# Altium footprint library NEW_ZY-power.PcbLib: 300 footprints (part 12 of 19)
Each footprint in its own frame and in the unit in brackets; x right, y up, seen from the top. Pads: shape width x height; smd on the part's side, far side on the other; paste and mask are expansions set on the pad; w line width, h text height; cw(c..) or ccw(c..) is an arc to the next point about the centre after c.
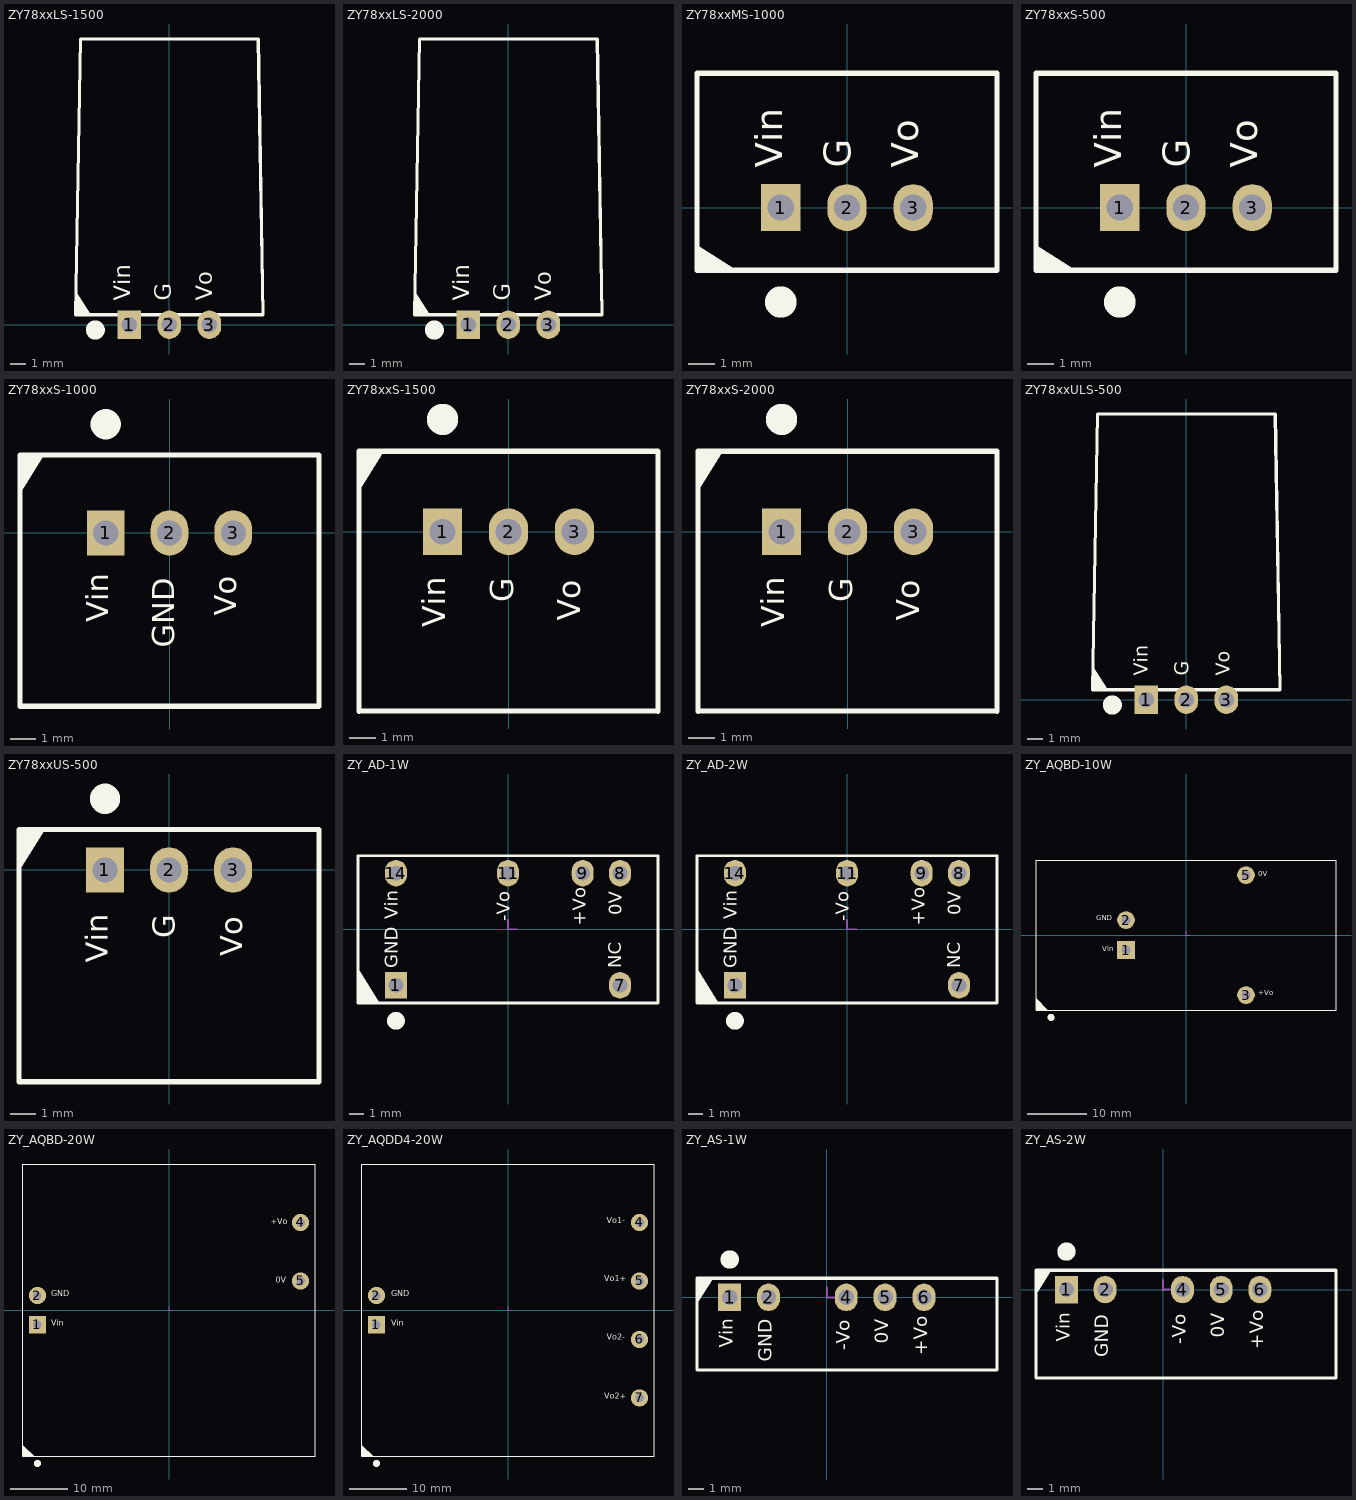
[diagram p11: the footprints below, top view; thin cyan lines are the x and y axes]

## ZY78xxLS-1500 [mm]
height 10
pads (3):
  rect 1.5x1.8 hole 1: 1(-2.54,0)
  oval 1.5x1.8 hole 1: 2(0,0) 3(2.54,0)
Top Overlay:
  circle w1: c-4.699,-0.327 r0.1
  region: -5.991,2.229 -5.991,0.644 -4.997,0.644
  lines w0.2: -5.95,0.644 -5.645,18.144 5.645,18.144 5.95,0.644 -5.95,0.644
  text "Vin" at -2.134,1.524 h1.78
  text "G" at 0.483,1.524 h1.78
  text "Vo" at 3.073,1.524 h1.78

## ZY78xxLS-2000 [mm]
height 10
pads (3):
  rect 1.5x1.8 hole 1: 1(-2.54,0)
  oval 1.5x1.8 hole 1: 2(0,0) 3(2.54,0)
Top Overlay:
  circle w1: c-4.699,-0.327 r0.1
  region: -5.991,2.229 -5.991,0.644 -4.997,0.644
  lines w0.2: -5.95,0.644 -5.645,18.144 5.645,18.144 5.95,0.644 -5.95,0.644
  text "Vin" at -2.134,1.524 h1.78
  text "G" at 0.483,1.524 h1.78
  text "Vo" at 3.073,1.524 h1.78

## ZY78xxMS-1000 [mm]
height 10.2
pads (3):
  rect 1.5x1.8 hole 1: 1(-2.54,0)
  oval 1.5x1.8 hole 1: 2(0,0) 3(2.54,0)
Top Overlay:
  circle w1: c-2.54,-3.625 r0.1
  region: -4.168,-2.441 -5.753,-2.441 -5.753,-1.447
  lines w0.2: -5.753,-2.4 5.753,-2.4 5.753,5.15 -5.753,5.15 -5.753,-2.4
  text "Vin" at -2.134,1.524 h1.78
  text "G" at 0.483,1.524 h1.78
  text "Vo" at 3.073,1.524 h1.78

## ZY78xxS-500 [mm]
pads (3):
  rect 1.5x1.8 hole 1: 1(-2.54,0)
  oval 1.5x1.8 hole 1: 2(0,0) 3(2.54,0)
Top Overlay:
  circle w1: c-2.54,-3.625 r0.1
  region: -4.168,-2.441 -5.753,-2.441 -5.753,-1.447
  lines w0.2: -5.753,-2.4 5.753,-2.4 5.753,5.15 -5.753,5.15 -5.753,-2.4
  text "Vo" at 3.073,1.524 h1.78
  text "G" at 0.483,1.524 h1.78
  text "Vin" at -2.134,1.524 h1.78

## ZY78xxS-1000 [mm]
height 17.5
pads (3):
  rect 1.5x1.8 hole 1: 1(-2.54,0)
  oval 1.5x1.8 hole 1: 2(0,0) 3(2.54,0)
Top Overlay:
  circle w1: c-2.54,4.325 r0.1
  region: -5.991,1.514 -5.991,3.1 -4.997,3.1
  lines w0.2: -5.95,-6.9 5.95,-6.9 5.95,3.1 -5.95,3.1 -5.95,-6.9
  text "Vo" at 2.946,-3.302 h1.52
  text "GND" at 0.483,-4.572 h1.52
  text "Vin" at -2.134,-3.562 h1.52

## ZY78xxS-1500 [mm]
height 17.5
pads (3):
  rect 1.5x1.8 hole 1: 1(-2.54,0)
  oval 1.5x1.8 hole 1: 2(0,0) 3(2.54,0)
Top Overlay:
  circle w1: c-2.54,4.325 r0.1
  region: -5.794,1.514 -5.794,3.1 -4.801,3.1
  lines w0.2: -5.753,-6.908 -5.753,3.1 5.753,3.1 5.753,-6.908 ; -5.753,-6.9 5.753,-6.9
  text "Vo" at 3.073,-3.423 h1.52
  text "G" at 0.483,-2.714 h1.52
  text "Vin" at -2.134,-3.683 h1.52

## ZY78xxS-2000 [mm]
height 17.5
pads (3):
  rect 1.5x1.8 hole 1: 1(-2.54,0)
  oval 1.5x1.8 hole 1: 2(0,0) 3(2.54,0)
Top Overlay:
  circle w1: c-2.54,4.325 r0.1
  region: -5.794,1.514 -5.794,3.1 -4.801,3.1
  lines w0.2: -5.753,-6.908 -5.753,3.1 5.753,3.1 5.753,-6.908 ; -5.753,-6.9 5.753,-6.9
  text "Vin" at -2.134,-3.683 h1.52
  text "G" at 0.483,-2.714 h1.52
  text "Vo" at 3.073,-3.423 h1.52

## ZY78xxULS-500 [mm]
height 10
pads (3):
  rect 1.5x1.8 hole 1: 1(-2.54,0)
  oval 1.5x1.8 hole 1: 2(0,0) 3(2.54,0)
Top Overlay:
  circle w1: c-4.699,-0.327 r0.1
  region: -5.991,2.229 -5.991,0.644 -4.997,0.644
  lines w0.2: -5.95,0.644 -5.645,18.144 5.645,18.144 5.95,0.644 -5.95,0.644
  text "Vin" at -2.134,1.524 h1.52
  text "G" at 0.483,1.524 h1.52
  text "Vo" at 3.073,1.524 h1.52

## ZY78xxUS-500 [mm]
height 17.5
pads (3):
  rect 1.5x1.8 hole 1: 1(-2.54,0)
  oval 1.5x1.8 hole 1: 2(0,0) 3(2.54,0)
Top Overlay:
  circle w1: c-2.54,2.825 r0.1
  region: -5.921,0.014 -5.921,1.6 -4.928,1.6
  lines w0.2: -5.95,-8.4 -5.95,1.6 5.95,1.6 5.95,-8.4 -5.95,-8.4
  text "Vin" at -2.134,-3.683 h1.52
  text "G" at 0.533,-2.714 h1.52
  text "Vo" at 3.2,-3.423 h1.52

## ZY_AD-1W [mm]
height 8.1
pads (6):
  rect 1.5x1.8 hole 1: 1(-7.62,-3.81)
  oval 1.5x1.8 hole 1: 7(7.62,-3.81) 8(7.62,3.81) 9(5.08,3.81) 11(0,3.81) 14(-7.62,3.81)
Top Overlay:
  circle w1: c-7.62,-6.225 r0.1
  region: -10.2,-2.67 -10.2,-5 -8.74,-5
  lines w0.2: -10.2,-5 -10.2,5 10.2,5 10.2,-5 -10.2,-5
  text "GND" at -7.188,-2.667 h1.52
  text "NC" at 8.001,-2.667 h1.52
  text "Vin" at -7.188,0.695 h1.52
  text "-Vo" at 0.432,0.539 h1.52
  text "+Vo" at 5.588,0.227 h1.52
  text "0V" at 8.052,0.967 h1.52
Mechanical 15:
  lines w0.127: 0,0.635 0,0 0.635,0

## ZY_AD-2W [mm]
height 8.1
pads (6):
  rect 1.5x1.8 hole 1: 1(-7.62,-3.81)
  oval 1.5x1.8 hole 1: 7(7.62,-3.81) 8(7.62,3.81) 9(5.08,3.81) 11(0,3.81) 14(-7.62,3.81)
Top Overlay:
  circle w1: c-7.62,-6.225 r0.1
  region: -10.2,-2.67 -10.2,-5 -8.74,-5
  lines w0.2: -10.2,-5 -10.2,5 10.2,5 10.2,-5 -10.2,-5
  text "GND" at -7.188,-2.667 h1.52
  text "NC" at 8.001,-2.667 h1.52
  text "Vin" at -7.188,0.695 h1.52
  text "-Vo" at 0.432,0.539 h1.52
  text "+Vo" at 5.588,0.227 h1.52
  text "0V" at 8.052,0.967 h1.52
Mechanical 15:
  lines w0.127: 0,0.635 0,0 0.635,0

## ZY_AQBD-10W [mm]
height 12.7
pads (4):
  rect 3x3 hole 1.5: 1(-10.16,-2.54)
  round 3 hole 1.5: 2(-10.16,2.54) 3(10.16,-10.16) 5(10.16,10.16)
Top Overlay:
  circle w1: c-22.86,-13.925 r0.1
  region: -25.4,-12.7 -23.425,-12.7 -25.4,-10.725
  lines w0.2: -25.4,-12.7 25.4,-12.7 25.4,12.7 -25.4,12.7 -25.4,-12.7
  text "Vin" at -14.179,-3.048 h1.52
  text "GND" at -15.189,2.159 h1.52
  text "0V" at 12.192,9.652 h1.52
  text "+Vo" at 12.192,-10.541 h1.52
Mechanical 15:
  lines w0.127: 0,0.635 0,0 0.635,0

## ZY_AQBD-20W [mm]
height 12.8
pads (4):
  rect 3x3 hole 1.5: 1(-22.86,-2.54)
  round 3 hole 1.5: 2(-22.86,2.54) 4(22.86,15.24) 5(22.86,5.08)
Top Overlay:
  circle w1: c-22.86,-26.625 r0.1
  region: -25.4,-25.4 -23.425,-25.4 -25.4,-23.425
  lines w0.2: -25.4,-25.4 25.4,-25.4 25.4,25.4 -25.4,25.4 -25.4,-25.4
  text "0V" at 18.517,4.447 h1.78
  text "+Vo" at 17.653,14.607 h1.78
  text "Vin" at -20.447,-3.046 h1.78
  text "GND" at -20.447,2.034 h1.78
Mechanical 15:
  lines w0.127: 0,0.635 0,0 0.635,0

## ZY_AQDD4-20W [mm]
pads (6):
  rect 3x3 hole 1.5: 1(-22.86,-2.54)
  round 3 hole 1.5: 2(-22.86,2.54) 4(22.86,15.24) 5(22.86,5.08) 6(22.86,-5.08) 7(22.86,-15.24)
Top Overlay:
  circle w1: c-22.86,-26.625 r0.1
  region: -25.4,-25.4 -23.425,-25.4 -25.4,-23.425
  lines w0.2: -25.4,-25.4 -25.4,25.4 25.4,25.4 25.4,-25.4 -25.4,-25.4
  text "GND" at -20.32,2.034 h1.78
  text "Vin" at -20.32,-3.046 h1.78
  text "Vo1+" at 16.764,4.699 h1.78
  text "Vo2+" at 16.764,-15.748 h1.78
  text "Vo2-" at 17.125,-5.461 h1.78
  text "Vo1-" at 17.125,14.732 h1.78
Mechanical 15:
  lines w0.127: 0,0.635 0,0 0.635,0

## ZY_AS-1W [mm] "定压输入隔离非稳压正、负双输出"
height 10
pads (5):
  rect 1.5x1.8 hole 1: 1(-6.35,0)
  oval 1.5x1.8 hole 1: 2(-3.81,0) 4(1.27,0) 5(3.81,0) 6(6.35,0)
Top Overlay:
  circle w1: c-6.35,2.475 r0.1
  region: -8.423,-0.336 -8.423,1.25 -7.429,1.25
  lines w0.2: -8.48,-4.75 -8.48,1.25 11.12,1.25 11.12,-4.75 -8.48,-4.75
  text "+Vo" at 6.858,-3.776 h1.52
  text "0V" at 4.318,-3.036 h1.52
  text "GND" at -3.302,-4.191 h1.52
  text "Vin" at -5.842,-3.308 h1.52
  text "-Vo" at 1.778,-3.464 h1.52
Mechanical 15:
  lines w0.127: 0,0.635 0,0 0.635,0

## ZY_AS-2W [mm] "定压输入隔离非稳压正、负双输出"
height 10
pads (5):
  rect 1.5x1.8 hole 1: 1(-6.35,0)
  oval 1.5x1.8 hole 1: 2(-3.81,0) 4(1.27,0) 5(3.81,0) 6(6.35,0)
Top Overlay:
  circle w1: c-6.35,2.495 r0.1
  region: -8.35,-0.316 -8.35,1.27 -7.356,1.27
  lines w0.2: 11.35,1.25 11.35,-5.8 -8.35,-5.8 -8.35,1.27 11.35,1.27
  text "-Vo" at 1.778,-3.591 h1.52
  text "Vin" at -5.842,-3.435 h1.52
  text "GND" at -3.302,-4.445 h1.52
  text "0V" at 4.318,-3.163 h1.52
  text "+Vo" at 6.858,-3.903 h1.52
Mechanical 15:
  lines w0.127: 0,0.635 0,0 0.635,0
